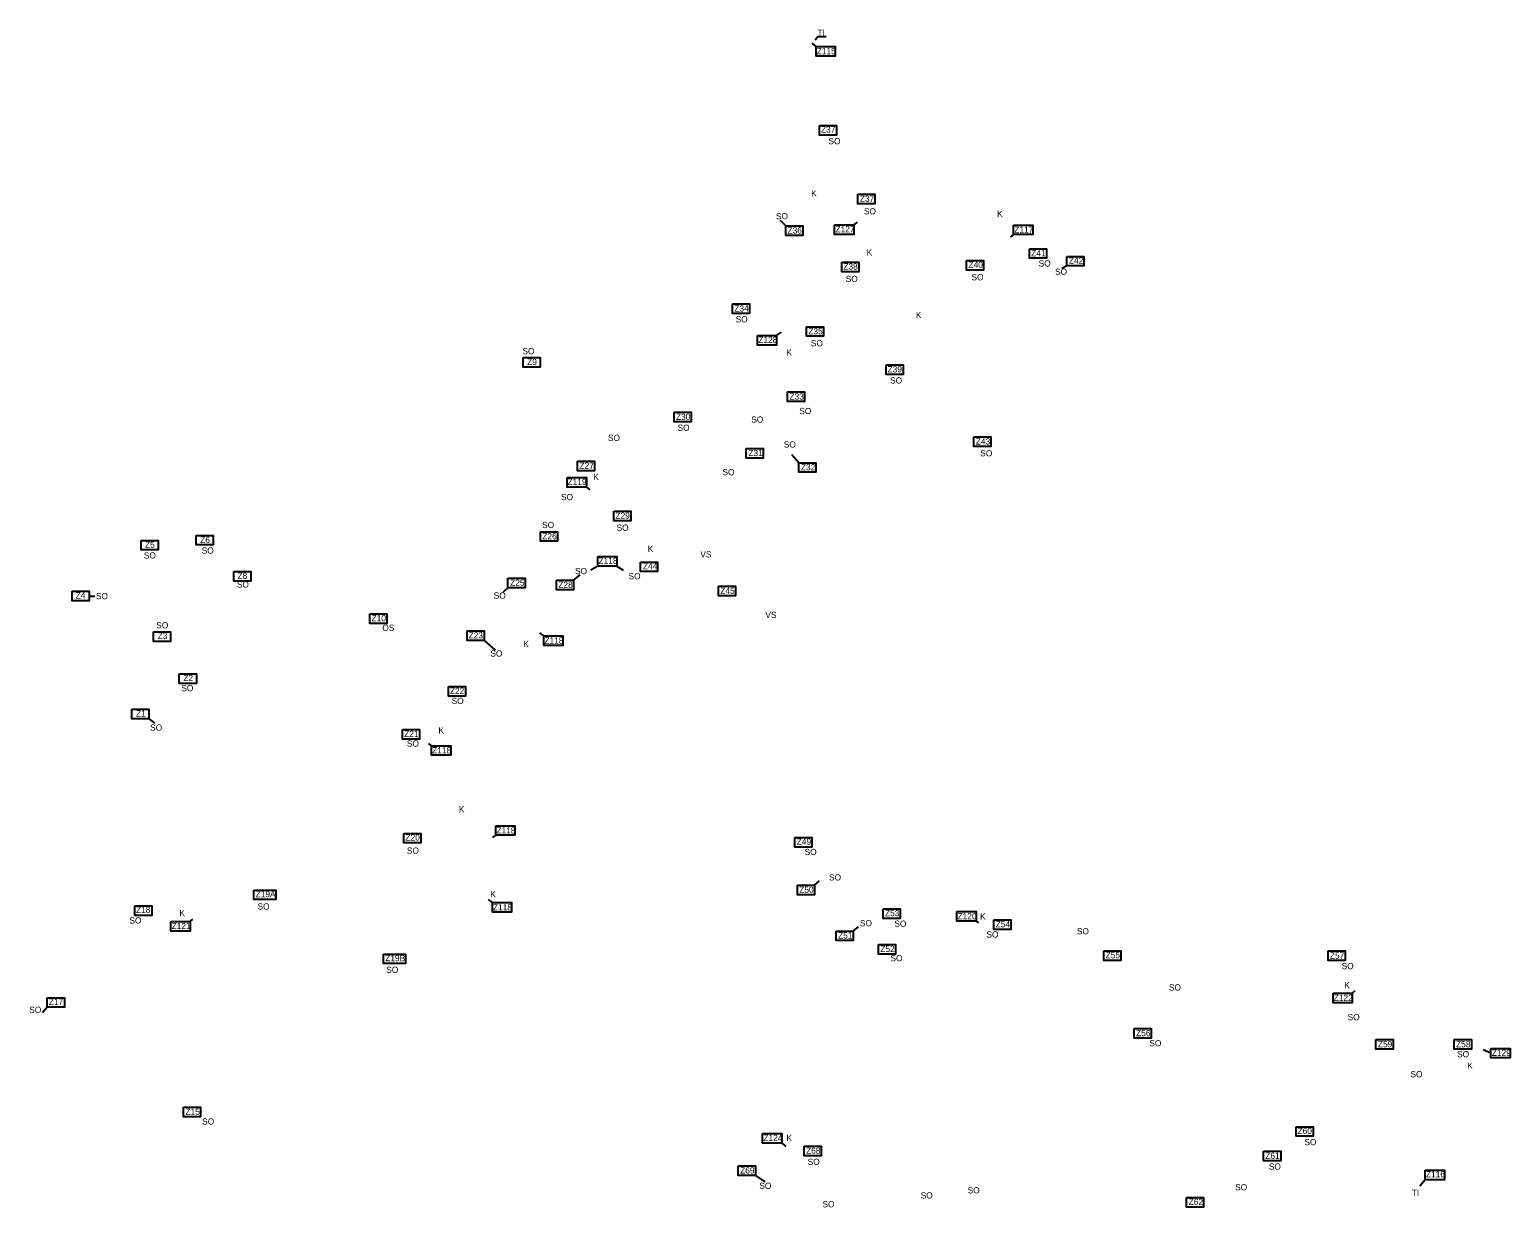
# Model space of a CAD drawing. Extents: x -443485 to -433023, y -1133480 to -1129775.
# Drawn here: x -443043 to -440666, y -1131666 to -1129775 of the extents above; entities that cross this region are included whole.
import ezdxf

# ---------------------------------------------------------------- set-up
doc = ezdxf.new("R2010")
doc.units = 0
for name, color, linetype in [('Vrstva 3', 7, 'Continuous'), ('Vrstva 4', 7, 'Continuous'), ('Vrstva 8', 7, 'Continuous')]:
    doc.layers.add(name, color=color, linetype=linetype)

msp = doc.modelspace()

# ---------------------------------------------------------------- linework, layer by layer
at = {"layer": 'Vrstva 3'}
for p, q in [((-441780.6, -1129802.1), (-441787.2, -1129796.7)), ((-441829.1, -1130090.3), (-441838, -1130081.7)), ((-441378.1, -1130154.6), (-441386.2, -1130158.4)), ((-441808.5, -1130470.4), (-441819.7, -1130457.7)), ((-442169.8, -1130659.1), (-442159.4, -1130650.4)), ((-442275.3, -1130671.3), (-442283.1, -1130678.3)), ((-442947.3, -1130684.5), (-442938.5, -1130684.6)), ((-442313.2, -1130756), (-442295.7, -1130771.4)), ((-442851.5, -1130881.4), (-442842.3, -1130888.4)), ((-441783.2, -1131148.9), (-441775.1, -1131141.9)), ((-441721, -1131222.3), (-441712.8, -1131215.4)), ((-443014.7, -1131344.8), (-443022.4, -1131353.5)), ((-441878.2, -1131614.7), (-441862.9, -1131625)), ((-440803, -1131621.5), (-440811.7, -1131631.9))]:
    msp.add_line(p, q, dxfattribs=at)
for points in [[(-441780.6, -1129802.1), (-441749.8, -1129802.1), (-441749.8, -1129817.5), (-441780.6, -1129817.5)], [(-441775.4, -1129929), (-441748, -1129929), (-441748, -1129944.4), (-441775.4, -1129944.4)], [(-441713.5, -1130039.3), (-441686.2, -1130039.3), (-441686.2, -1130054.7), (-441713.5, -1130054.7)], [(-441829.1, -1130090.3), (-441801.8, -1130090.3), (-441801.8, -1130105.7), (-441829.1, -1130105.7)], [(-441438.1, -1130126.8), (-441410.7, -1130126.8), (-441410.7, -1130142.2), (-441438.1, -1130142.2)], [(-441739.6, -1130148.5), (-441712.2, -1130148.5), (-441712.2, -1130163.9), (-441739.6, -1130163.9)], [(-441539.4, -1130145.7), (-441512, -1130145.7), (-441512, -1130161.1), (-441539.4, -1130161.1)], [(-441378.1, -1130139.2), (-441350.7, -1130139.2), (-441350.7, -1130154.6), (-441378.1, -1130154.6)], [(-441915.1, -1130215.4), (-441887.7, -1130215.4), (-441887.7, -1130230.8), (-441915.1, -1130230.8)], [(-441796.3, -1130252.1), (-441768.9, -1130252.1), (-441768.9, -1130267.5), (-441796.3, -1130267.5)], [(-442250.7, -1130301.4), (-442223.3, -1130301.4), (-442223.3, -1130316.8), (-442250.7, -1130316.8)], [(-441668.4, -1130313.2), (-441641, -1130313.2), (-441641, -1130328.6), (-441668.4, -1130328.6)], [(-441826.6, -1130356.8), (-441799.2, -1130356.8), (-441799.2, -1130372.2), (-441826.6, -1130372.2)], [(-442008.5, -1130389.3), (-441981.2, -1130389.3), (-441981.2, -1130404.7), (-442008.5, -1130404.7)], [(-441527.5, -1130428.9), (-441500.2, -1130428.9), (-441500.2, -1130444.3), (-441527.5, -1130444.3)], [(-441893, -1130447.6), (-441865.6, -1130447.6), (-441865.6, -1130463), (-441893, -1130463)], [(-442163.9, -1130468.1), (-442136.5, -1130468.1), (-442136.5, -1130483.5), (-442163.9, -1130483.5)], [(-441808.5, -1130470.4), (-441781.1, -1130470.4), (-441781.1, -1130485.8), (-441808.5, -1130485.8)], [(-442105.4, -1130548.2), (-442078, -1130548.2), (-442078, -1130563.6), (-442105.4, -1130563.6)], [(-442222.8, -1130581.2), (-442195.5, -1130581.2), (-442195.5, -1130596.5), (-442222.8, -1130596.5)], [(-442864.1, -1130595.1), (-442836.8, -1130595.1), (-442836.8, -1130610.4), (-442864.1, -1130610.4)], [(-442775.7, -1130587.1), (-442748.3, -1130587.1), (-442748.3, -1130602.5), (-442775.7, -1130602.5)], [(-442062.5, -1130629.9), (-442035.1, -1130629.9), (-442035.1, -1130645.2), (-442062.5, -1130645.2)], [(-442715, -1130645.3), (-442687.7, -1130645.3), (-442687.7, -1130660.7), (-442715, -1130660.7)], [(-442275.3, -1130655.9), (-442247.9, -1130655.9), (-442247.9, -1130671.3), (-442275.3, -1130671.3)], [(-442974.7, -1130676.8), (-442947.3, -1130676.8), (-442947.3, -1130692.2), (-442974.7, -1130692.2)], [(-442197.1, -1130659.1), (-442169.8, -1130659.1), (-442169.8, -1130674.5), (-442197.1, -1130674.5)], [(-441937.3, -1130668.5), (-441909.9, -1130668.5), (-441909.9, -1130683.9), (-441937.3, -1130683.9)], [(-442497.1, -1130713.3), (-442469.7, -1130713.3), (-442469.7, -1130728.7), (-442497.1, -1130728.7)], [(-442844.2, -1130741.8), (-442816.9, -1130741.8), (-442816.9, -1130757.2), (-442844.2, -1130757.2)], [(-442340.6, -1130740.6), (-442313.2, -1130740.6), (-442313.2, -1130756), (-442340.6, -1130756)], [(-442802.8, -1130809.3), (-442775.4, -1130809.3), (-442775.4, -1130824.7), (-442802.8, -1130824.7)], [(-442370.9, -1130829.7), (-442343.6, -1130829.7), (-442343.6, -1130845.1), (-442370.9, -1130845.1)], [(-442878.9, -1130866.1), (-442851.5, -1130866.1), (-442851.5, -1130881.4), (-442878.9, -1130881.4)], [(-442444.7, -1130898.7), (-442417.3, -1130898.7), (-442417.3, -1130914.1), (-442444.7, -1130914.1)], [(-442442.5, -1131065.5), (-442415.2, -1131065.5), (-442415.2, -1131080.9), (-442442.5, -1131080.9)], [(-441815, -1131072), (-441787.6, -1131072), (-441787.6, -1131087.4), (-441815, -1131087.4)], [(-442683.1, -1131156.5), (-442647.9, -1131156.5), (-442647.9, -1131171.9), (-442683.1, -1131171.9)], [(-441810.6, -1131148.9), (-441783.2, -1131148.9), (-441783.2, -1131164.3), (-441810.6, -1131164.3)], [(-442874.4, -1131181.7), (-442847.1, -1131181.7), (-442847.1, -1131197.1), (-442874.4, -1131197.1)], [(-441673.2, -1131186.9), (-441645.8, -1131186.9), (-441645.8, -1131202.2), (-441673.2, -1131202.2)], [(-441495.6, -1131204.2), (-441468.2, -1131204.2), (-441468.2, -1131219.6), (-441495.6, -1131219.6)], [(-441748.4, -1131222.3), (-441721, -1131222.3), (-441721, -1131237.7), (-441748.4, -1131237.7)], [(-441680.5, -1131244), (-441653.2, -1131244), (-441653.2, -1131259.4), (-441680.5, -1131259.4)], [(-442475.1, -1131259.2), (-442439.9, -1131259.2), (-442439.9, -1131274.6), (-442475.1, -1131274.6)], [(-441319, -1131254), (-441291.6, -1131254), (-441291.6, -1131269.4), (-441319, -1131269.4)], [(-440958.8, -1131254.3), (-440931.4, -1131254.3), (-440931.4, -1131269.7), (-440958.8, -1131269.7)], [(-443014.7, -1131329.4), (-442987.3, -1131329.4), (-442987.3, -1131344.8), (-443014.7, -1131344.8)], [(-441270.2, -1131379), (-441242.8, -1131379), (-441242.8, -1131394.4), (-441270.2, -1131394.4)], [(-440882, -1131396.5), (-440854.6, -1131396.5), (-440854.6, -1131411.9), (-440882, -1131411.9)], [(-440756.3, -1131396.5), (-440728.9, -1131396.5), (-440728.9, -1131411.9), (-440756.3, -1131411.9)], [(-442795.9, -1131505.2), (-442768.5, -1131505.2), (-442768.5, -1131520.6), (-442795.9, -1131520.6)], [(-441010.2, -1131536.4), (-440982.9, -1131536.4), (-440982.9, -1131551.8), (-441010.2, -1131551.8)], [(-441799.8, -1131567.7), (-441772.4, -1131567.7), (-441772.4, -1131583.1), (-441799.8, -1131583.1)], [(-441062.3, -1131575.9), (-441035, -1131575.9), (-441035, -1131591.3), (-441062.3, -1131591.3)], [(-441905.5, -1131599.3), (-441878.2, -1131599.3), (-441878.2, -1131614.7), (-441905.5, -1131614.7)], [(-440803, -1131606.1), (-440772.3, -1131606.1), (-440772.3, -1131621.5), (-440803, -1131621.5)], [(-441186, -1131650.3), (-441158.6, -1131650.3), (-441158.6, -1131665.7), (-441186, -1131665.7)]]:
    msp.add_lwpolyline(points, close=True, dxfattribs=at)
at = {"layer": 'Vrstva 4'}
msp.add_lwpolyline([(-441764.3, -1129786.7), (-441777.7, -1129786.7), (-441781.9, -1129791.9)], dxfattribs=at)
at = {"layer": 'Vrstva 8'}
for p, q in [((-441720.1, -1130088.6), (-441714.3, -1130084)), ((-441463.6, -1130104.2), (-441469.4, -1130108.5)), ((-441844, -1130266.2), (-441836.1, -1130260.9)), ((-442149.3, -1130509.6), (-442143.6, -1130514.2)), ((-442131, -1130636.5), (-442142.2, -1130643.1)), ((-442100.3, -1130636.5), (-442090.5, -1130642.7)), ((-442217.8, -1130748.4), (-442224.2, -1130743.6)), ((-442398, -1130924.7), (-442402.3, -1130921.1)), ((-442294.8, -1131068.6), (-442299.8, -1131072.4)), ((-442300.3, -1131176.7), (-442306.7, -1131171.9)), ((-442785.3, -1131206.9), (-442780.8, -1131203.4)), ((-441523.9, -1131206.4), (-441520.2, -1131209.2)), ((-440920.2, -1131322), (-440915.5, -1131317.9)), ((-440697.5, -1131418.4), (-440709.9, -1131413.3)), ((-441835.8, -1131562.7), (-441829.5, -1131568.4))]:
    msp.add_line(p, q, dxfattribs=at)
for points in [[(-441750.9, -1130088.6), (-441720.1, -1130088.6), (-441720.1, -1130104), (-441750.9, -1130104)], [(-441463.6, -1130088.8), (-441432.8, -1130088.8), (-441432.8, -1130104.2), (-441463.6, -1130104.2)], [(-441874.8, -1130266.2), (-441844, -1130266.2), (-441844, -1130281.6), (-441874.8, -1130281.6)], [(-442180.1, -1130494.2), (-442149.3, -1130494.2), (-442149.3, -1130509.6), (-442180.1, -1130509.6)], [(-442131, -1130621.1), (-442100.3, -1130621.1), (-442100.3, -1130636.5), (-442131, -1130636.5)], [(-442217.8, -1130748.4), (-442187, -1130748.4), (-442187, -1130763.8), (-442217.8, -1130763.8)], [(-442398, -1130924.7), (-442367.2, -1130924.7), (-442367.2, -1130940.1), (-442398, -1130940.1)], [(-442294.8, -1131053.2), (-442264, -1131053.2), (-442264, -1131068.6), (-442294.8, -1131068.6)], [(-442300.3, -1131176.7), (-442269.5, -1131176.7), (-442269.5, -1131192.1), (-442300.3, -1131192.1)], [(-441554.7, -1131191), (-441523.9, -1131191), (-441523.9, -1131206.4), (-441554.7, -1131206.4)], [(-442816.1, -1131206.9), (-442785.3, -1131206.9), (-442785.3, -1131222.3), (-442816.1, -1131222.3)], [(-440951, -1131322), (-440920.2, -1131322), (-440920.2, -1131337.4), (-440951, -1131337.4)], [(-440697.5, -1131410.7), (-440666.8, -1131410.7), (-440666.8, -1131426.1), (-440697.5, -1131426.1)], [(-441866.6, -1131547.3), (-441835.8, -1131547.3), (-441835.8, -1131562.7), (-441866.6, -1131562.7)]]:
    msp.add_lwpolyline(points, close=True, dxfattribs=at)

# ---------------------------------------------------------------- texts
at = {"layer": 'Vrstva 3'}
for s, p in [('Z115', (-441779.6, -1129814.6)), ('Z37', (-441772.8, -1129940.6)), ('Z37', (-441710.4, -1130051.5)), ('Z36', (-441826.5, -1130102.5)), ('Z41', (-441435.5, -1130139.1)), ('Z38', (-441736.9, -1130160.4)), ('Z40', (-441536, -1130157.5)), ('Z42', (-441374.9, -1130151)), ('Z34', (-441911.9, -1130227.7)), ('Z35', (-441793.1, -1130264.3)), ('Z9', (-442244.4, -1130313.5)), ('Z39', (-441665.9, -1130325.4)), ('Z33', (-441823.4, -1130369)), ('Z30', (-442005.5, -1130401.6)), ('Z43', (-441524.3, -1130441.2)), ('Z31', (-441889.4, -1130459.9)), ('Z27', (-442160.4, -1130480.1)), ('Z32', (-441805, -1130482.6)), ('Z29', (-442102.7, -1130560.4)), ('Z26', (-442220.1, -1130593.6)), ('Z5', (-442857.7, -1130606.9)), ('Z6', (-442769.2, -1130599.2)), ('Z44', (-442058.6, -1130641.4)), ('Z8', (-442709.3, -1130657)), ('Z25', (-442271.7, -1130668)), ('Z4', (-442969.1, -1130688.5)), ('Z28', (-442194.4, -1130671.3)), ('Z45', (-441934.4, -1130681)), ('Z10', (-442494.1, -1130725)), ('Z3', (-442837.5, -1130753.5)), ('Z23', (-442338.4, -1130752.5)), ('Z2', (-442796.3, -1130821.1)), ('Z22', (-442368.4, -1130841.6)), ('Z1', (-442872.3, -1130878.1)), ('Z21', (-442441.8, -1130910.7)), ('Z20', (-442439.7, -1131077)), ('Z49', (-441811.7, -1131083.8)), ('Z50', (-441807.7, -1131160.9)), ('Z19A', (-442680.2, -1131168)), ('Z18', (-442872.3, -1131193.4)), ('Z53', (-441670.1, -1131198.5)), ('Z51', (-441745.4, -1131234.4)), ('Z54', (-441492.5, -1131216.4)), ('Z52', (-441677.6, -1131256)), ('Z19B', (-442472.2, -1131270.7)), ('Z55', (-441315.9, -1131266)), ('Z57', (-440956, -1131266.7)), ('Z17', (-443012.2, -1131341)), ('Z56', (-441267.1, -1131391.1)), ('Z59', (-440878.9, -1131409)), ('Z58', (-440753.5, -1131409)), ('Z15', (-442792.9, -1131517.3)), ('Z60', (-441007.9, -1131548.3)), ('Z68', (-441796.7, -1131580)), ('Z61', (-441059.6, -1131588.1)), ('Z69', (-441902.5, -1131611.6)), ('Z116', (-440801.8, -1131617.8)), ('Z62', (-441182.6, -1131662.1))]:
    msp.add_text(s, height=10, dxfattribs=at).set_placement(p)
at = {"layer": 'Vrstva 4'}
for s, p in [('TI', (-441778.4, -1129785.1)), ('SO', (-441760.9, -1129959.2)), ('K', (-441788.5, -1130042.9)), ('SO', (-441703.9, -1130071.8)), ('SO', (-441845.2, -1130079.6)), ('K', (-441490.1, -1130075.8)), ('K', (-441699.6, -1130137.8)), ('SO', (-441423.4, -1130155.4)), ('SO', (-441397.1, -1130168.7)), ('SO', (-441733.1, -1130180.3)), ('SO', (-441531.3, -1130177.6)), ('K', (-441620.6, -1130238.2)), ('SO', (-441909.8, -1130245.1)), ('SO', (-441789.1, -1130283.6)), ('SO', (-442252, -1130296.2)), ('K', (-441828.5, -1130298.3)), ('SO', (-441661.9, -1130343.3)), ('SO', (-441884.8, -1130406.2)), ('SO', (-441807.7, -1130392.4)), ('SO', (-442003.1, -1130419.2)), ('SO', (-442114.8, -1130435.6)), ('SO', (-441832.5, -1130446.1)), ('SO', (-441517.1, -1130460.2)), ('K', (-442138.4, -1130498.1)), ('SO', (-441930.9, -1130490.5)), ('SO', (-442190.1, -1130530.5)), ('SO', (-442220.5, -1130575.4)), ('SO', (-442100.9, -1130579.7)), ('SO', (-442766.8, -1130616.4)), ('K', (-442050.9, -1130613.8)), ('SO', (-442859.7, -1130624.2)), ('VS', (-441966.5, -1130622.5)), ('SO', (-442167.6, -1130649.4)), ('SO', (-442081.7, -1130657.6)), ('SO', (-442936.7, -1130689.5)), ('SO', (-442710.4, -1130670.9)), ('SO', (-442298.1, -1130688.6)), ('SO', (-442839.7, -1130736.4)), ('VS', (-441862, -1130719.8)), ('OS', (-442476.9, -1130740.4)), ('SO', (-442303.5, -1130781.7)), ('K', (-442250.7, -1130766.3)), ('SO', (-442799.5, -1130837.3)), ('SO', (-442365.6, -1130857.8)), ('SO', (-442849.6, -1130900.6)), ('K', (-442386.9, -1130905.2)), ('SO', (-442437.5, -1130926.3)), ('K', (-442354, -1131031.8)), ('SO', (-442437.5, -1131098.2)), ('SO', (-441799.1, -1131100.4)), ('SO', (-441759.9, -1131141.1)), ('SO', (-442677.2, -1131187.8)), ('K', (-442303.6, -1131168.2)), ('SO', (-442882.9, -1131210.3)), ('K', (-442802.6, -1131198.5)), ('SO', (-441710.3, -1131214.7)), ('K', (-441517.4, -1131204)), ('SO', (-441655.1, -1131215.5)), ('SO', (-441507.3, -1131232.8)), ('SO', (-441362.1, -1131227.7)), ('SO', (-441661.3, -1131270.8)), ('SO', (-440937.1, -1131283.6)), ('SO', (-442470.6, -1131289.5)), ('SO', (-441214.4, -1131317.8)), ('K', (-440932.9, -1131314.1)), ('SO', (-443043.6, -1131353.8)), ('SO', (-440927.5, -1131365.5)), ('SO', (-441245.8, -1131407.4)), ('SO', (-440751.9, -1131425)), ('K', (-440735.6, -1131443.4)), ('SO', (-440826.7, -1131457.1)), ('SO', (-442766.1, -1131533.1)), ('K', (-441828.3, -1131559.4)), ('SO', (-440996.9, -1131566.1)), ('SO', (-441794.2, -1131597.8)), ('SO', (-441054, -1131605.4)), ('SO', (-441871.8, -1131636.4)), ('SO', (-441108.1, -1131638.6)), ('SO', (-441770.4, -1131665.8)), ('SO', (-441612.8, -1131651.7)), ('SO', (-441537.4, -1131643.6)), ('TI', (-440824.7, -1131647.6))]:
    msp.add_text(s, height=10, dxfattribs=at).set_placement(p)
at = {"layer": 'Vrstva 8'}
for s, p in [('Z127', (-441749.5, -1130100.6)), ('Z117', (-441462.5, -1130101.2)), ('Z128', (-441873.4, -1130278.2)), ('Z119', (-442179.6, -1130506.2)), ('Z118', (-442129.9, -1130632.9)), ('Z118', (-442216.7, -1130760.9)), ('Z118', (-442396.9, -1130937.1)), ('Z118', (-442293.7, -1131065.7)), ('Z118', (-442299.3, -1131189.2)), ('Z120', (-441553.6, -1131203.5)), ('Z121', (-442815.1, -1131219.3)), ('Z122', (-440949.9, -1131334.5)), ('Z129', (-440696.1, -1131422.7)), ('Z124', (-441865.2, -1131559.3))]:
    msp.add_text(s, height=10, dxfattribs=at).set_placement(p)

doc.saveas('drawing.dxf')
